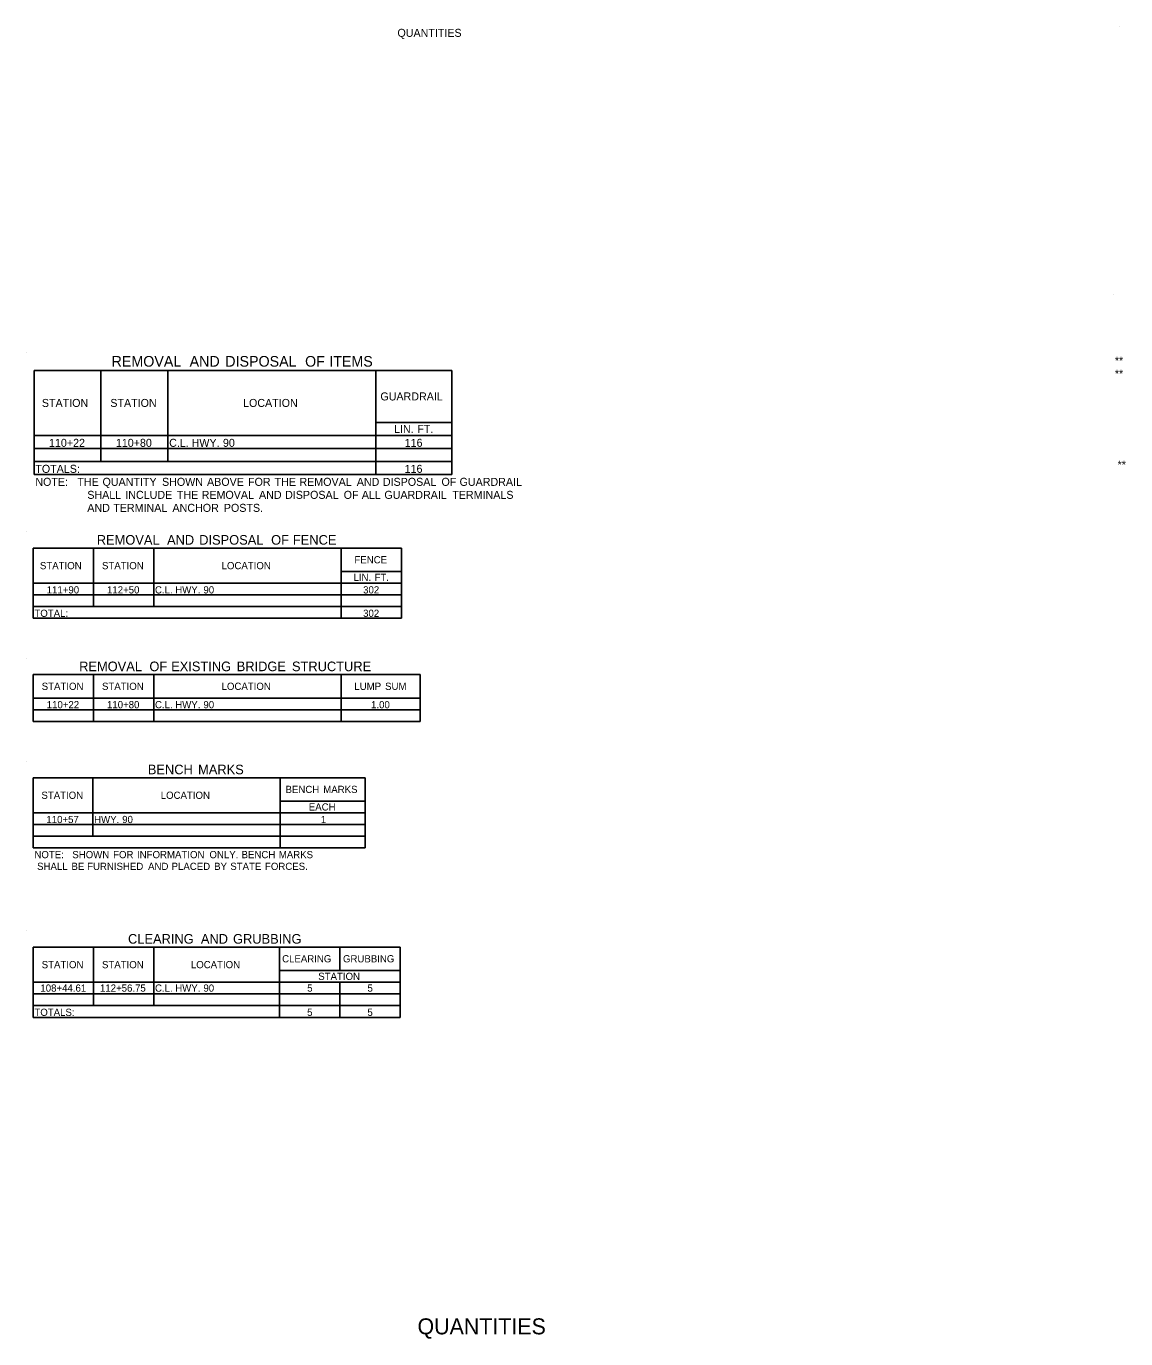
# Model space of a CAD drawing. Extents: x 120 to 5602, y 34 to 1048.
# Drawn here: x 1265 to 2090, y 34 to 1019 of the extents above; entities that cross this region are included whole.
import ezdxf

# ---------------------------------------------------------------- set-up
doc = ezdxf.new("R2010")
doc.units = 0
for name, color, linetype in [('Default', 7, 'Continuous'), ('R_Annotation', 7, 'Continuous'), ('R_Logo', 7, 'Continuous'), ('STAMP', 7, 'Continuous')]:
    doc.layers.add(name, color=color, linetype=linetype)

msp = doc.modelspace()

# ---------------------------------------------------------------- linework, layer by layer
at = {"layer": 'Default'}
for p, q in [((1270.81, 760.61), (1584.27, 760.61)), ((1270.81, 682.61), (1270.81, 760.61)), ((1270.81, 682.61), (1270.81, 760.61)), ((1321.02, 692.36), (1321.02, 760.61)), ((1371.24, 692.36), (1371.24, 760.61)), ((1527.24, 682.61), (1527.24, 760.61)), ((1584.27, 682.61), (1584.27, 760.61)), ((1584.27, 682.61), (1584.27, 760.61)), ((1527.24, 721.61), (1584.27, 721.61)), ((1270.81, 711.86), (1584.27, 711.86)), ((1321.02, 692.36), (1321.02, 711.86)), ((1371.24, 692.36), (1371.24, 711.86)), ((1527.24, 682.61), (1527.24, 711.86)), ((1270.81, 702.11), (1584.27, 702.11)), ((1270.81, 692.36), (1584.27, 692.36)), ((1527.24, 692.36), (1584.27, 692.36)), ((1270.81, 682.61), (1584.27, 682.61)), ((1270.23, 627.41), (1546.48, 627.41)), ((1270.23, 574.71), (1270.23, 627.41)), ((1270.23, 574.71), (1270.23, 627.41)), ((1315.47, 583.49), (1315.47, 627.41)), ((1360.7, 583.49), (1360.7, 627.41)), ((1501.24, 574.71), (1501.24, 627.41)), ((1546.48, 574.71), (1546.48, 627.41)), ((1546.48, 574.71), (1546.48, 627.41)), ((1270.23, 601.06), (1546.48, 601.06)), ((1315.47, 583.49), (1315.47, 601.06)), ((1360.7, 583.49), (1360.7, 601.06)), ((1501.24, 609.84), (1546.48, 609.84)), ((1501.24, 574.71), (1501.24, 601.06)), ((1270.23, 592.27), (1546.48, 592.27)), ((1270.23, 583.49), (1546.48, 583.49)), ((1270.23, 574.71), (1546.48, 574.71)), ((1270.23, 532.53), (1560.53, 532.53)), ((1270.23, 497.4), (1270.23, 532.53)), ((1270.23, 497.4), (1270.23, 532.53)), ((1315.47, 497.4), (1315.47, 532.53)), ((1360.7, 497.4), (1360.7, 532.53)), ((1501.24, 497.4), (1501.24, 532.53)), ((1560.53, 497.4), (1560.53, 532.53)), ((1560.53, 497.4), (1560.53, 532.53)), ((1270.23, 514.96), (1560.53, 514.96)), ((1315.47, 497.4), (1315.47, 514.96)), ((1360.7, 497.4), (1360.7, 514.96)), ((1501.24, 497.4), (1501.24, 514.96)), ((1270.23, 506.18), (1560.53, 506.18)), ((1270.23, 497.4), (1560.53, 497.4)), ((1270.23, 455.22), (1519.25, 455.22)), ((1270.23, 402.52), (1270.23, 455.22)), ((1270.23, 402.52), (1270.23, 455.22)), ((1315.03, 411.3), (1315.03, 455.22)), ((1455.57, 402.52), (1455.57, 455.22)), ((1519.25, 402.52), (1519.25, 455.22)), ((1455.57, 437.65), (1519.25, 437.65)), ((1519.25, 402.52), (1519.25, 437.65)), ((1270.23, 428.87), (1519.25, 428.87)), ((1455.57, 402.52), (1455.57, 428.87)), ((1270.23, 420.09), (1519.25, 420.09)), ((1270.23, 411.3), (1519.25, 411.3)), ((1270.23, 402.52), (1519.25, 402.52)), ((1270.23, 328.2), (1545.6, 328.2)), ((1270.23, 275.5), (1270.23, 328.2)), ((1270.23, 275.5), (1270.23, 328.2)), ((1315.47, 284.28), (1315.47, 328.2)), ((1360.7, 284.28), (1360.7, 328.2)), ((1455.13, 275.5), (1455.13, 328.2)), ((1500.36, 310.63), (1500.36, 328.2)), ((1545.6, 275.5), (1545.6, 328.2)), ((1545.6, 310.63), (1545.6, 328.2)), ((1455.13, 310.63), (1545.6, 310.63)), ((1455.13, 284.28), (1455.13, 310.63)), ((1270.23, 301.85), (1545.6, 301.85)), ((1315.47, 284.28), (1315.47, 301.85)), ((1360.7, 284.28), (1360.7, 301.85)), ((1500.36, 275.5), (1500.36, 301.85)), ((1500.36, 275.5), (1500.36, 301.85)), ((1545.6, 284.28), (1545.6, 301.85)), ((1270.23, 293.07), (1545.6, 293.07)), ((1270.23, 284.28), (1545.6, 284.28)), ((1360.7, 284.28), (1545.6, 284.28)), ((1270.23, 275.5), (1545.6, 275.5))]:
    msp.add_line(p, q, dxfattribs=at)
at = {"layer": 'STAMP'}
for p, q in [((2085.27, 1018.7), (2085.27, 1018.7)), ((2080.89, 817.41), (2080.89, 817.41)), ((1264.96, 774.26), (1264.96, 774.26)), ((1264.96, 639.7), (1264.96, 639.7)), ((1264.96, 544.83), (1264.96, 544.83)), ((1264.96, 467.52), (1264.96, 467.52)), ((1264.96, 340.5), (1264.96, 340.5))]:
    msp.add_line(p, q, dxfattribs=at)

# ---------------------------------------------------------------- texts
at = {"layer": 'Default'}
for s, height, p in [('REMOVAL', 8, (1329.01, 763.43)), (' AND', 8, (1384.57, 763.43)), (' DISPOSAL', 8, (1411.34, 763.43)), (' OF', 8, (1471.25, 763.43)), (' ITEMS', 8, (1489.36, 763.43)), ('**', 6, (2081.86, 764.99)), ('**', 6, (2081.86, 755.24)), ('STATION', 6, (1276.69, 733.23)), ('STATION', 6, (1328.07, 733.23)), ('LOCATION', 6, (1427.68, 733.23)), ('GUARDRAIL', 6, (1530.73, 738.11)), ('LIN.', 6, (1540.97, 713.73)), (' FT.', 6, (1556.22, 713.73)), ('110+22', 6, (1282.04, 703.31)), ('110+80', 6, (1332.23, 703.31)), ('C.L.', 6, (1372.21, 703.31)), (' HWY.', 6, (1386.85, 703.31)), (' 90', 6, (1410.33, 703.31)), ('116', 6, (1548.96, 703.31)), ('TOTALS:', 6, (1271.79, 683.81)), ('116', 6, (1548.91, 683.81)), ('**', 6, (2083.92, 686.99)), ('NOTE:', 6, (1271.79, 674.06)), ('   THE', 6, (1296.67, 674.06)), (' QUANTITY', 6, (1319.98, 674.06)), (' SHOWN', 6, (1364.63, 674.06)), (' ABOVE', 6, (1398.41, 674.06)), (' FOR', 6, (1429.18, 674.06)), (' THE', 6, (1449.09, 674.06)), (' REMOVAL', 6, (1467.74, 674.06)), (' AND', 6, (1510.77, 674.06)), (' DISPOSAL', 6, (1530.35, 674.06)), (' OF', 6, (1574.32, 674.06)), (' GUARDRAIL', 6, (1587.91, 674.06)), ('SHALL', 6, (1310.79, 664.31)), (' INCLUDE', 6, (1337.05, 664.31)), (' THE', 6, (1375.73, 664.31)), (' REMOVAL', 6, (1394.38, 664.31)), (' AND', 6, (1437.41, 664.31)), (' DISPOSAL', 6, (1456.99, 664.31)), (' OF', 6, (1500.96, 664.31)), (' ALL', 6, (1514.54, 664.31)), (' GUARDRAIL', 6, (1531.49, 664.31)), (' TERMINALS', 6, (1582.43, 664.31)), ('AND', 6, (1310.79, 654.56)), (' TERMINAL', 6, (1328.04, 654.56)), (' ANCHOR', 6, (1372.46, 654.56)), (' POSTS.', 6, (1411.01, 654.56)), ('REMOVAL', 7.207, (1317.91, 629.95)), (' AND', 7.207, (1367.96, 629.95)), (' DISPOSAL', 7.207, (1392.08, 629.95)), (' OF', 7.207, (1446.05, 629.95)), (' FENCE', 7.207, (1462.37, 629.95)), ('FENCE', 5.405, (1511.24, 615.92)), ('STATION ', 5.405, (1275.23, 611.53)), ('STATION', 5.405, (1321.81, 611.53)), ('LOCATION', 5.405, (1411.55, 611.53)), ('LIN.', 5.405, (1510.53, 602.75)), (' FT.', 5.405, (1524.28, 602.75)), ('111+90', 5.405, (1280.33, 593.35)), ('112+50', 5.405, (1325.57, 593.35)), ('C.L.', 5.405, (1361.58, 593.35)), (' HWY.', 5.405, (1374.77, 593.35)), (' 90', 5.405, (1395.92, 593.35)), ('302', 5.405, (1517.76, 593.35)), ('TOTAL:', 5.405, (1271.11, 575.79)), ('302', 5.405, (1517.75, 575.79)), ('REMOVAL', 7.207, (1304.67, 535.07)), (' OF', 7.207, (1354.72, 535.07)), (' EXISTING', 7.207, (1371.04, 535.07)), (' BRIDGE', 7.207, (1420.23, 535.07)), (' STRUCTURE', 7.207, (1461.69, 535.07)), ('STATION', 5.405, (1276.58, 521.04)), ('STATION', 5.405, (1321.81, 521.04)), ('LOCATION', 5.405, (1411.55, 521.04)), ('LUMP', 5.405, (1511.19, 521.04)), (' SUM', 5.405, (1532.24, 521.04)), ('110+22', 5.405, (1280.35, 507.26)), ('110+80', 5.405, (1325.57, 507.26)), ('C.L.', 5.405, (1361.58, 507.26)), (' HWY.', 5.405, (1374.77, 507.26)), (' 90', 5.405, (1395.92, 507.26)), ('1.00', 5.405, (1523.72, 507.26)), ('BENCH', 7.207, (1356.21, 457.76)), (' MARKS', 7.207, (1391.25, 457.76)), ('STATION', 5.405, (1276.36, 439.34)), ('LOCATION', 5.405, (1365.88, 439.34)), ('BENCH', 5.405, (1459.56, 443.73)), (' MARKS', 5.405, (1485.83, 443.73)), ('EACH', 5.405, (1477, 430.56)), ('110+57', 5.405, (1280.1, 421.17)), ('HWY.', 5.405, (1315.91, 421.17)), (' 90', 5.405, (1334.97, 421.17)), ('1', 5.41, (1486, 421.17)), ('NOTE:', 5.405, (1271.11, 394.82)), ('   SHOWN', 5.405, (1293.53, 394.82)), (' FOR', 5.405, (1328.15, 394.82)), (' INFORMATION', 5.4053, (1346.09, 394.82)), (' ONLY.', 5.405, (1400.44, 394.82)), (' BENCH', 5.405, (1424.54, 394.82)), (' MARKS', 5.405, (1452.47, 394.82)), (' SHALL', 5.405, (1271.11, 386.03)), (' BE', 5.405, (1296.87, 386.03)), (' FURNISHED', 5.405, (1308.64, 386.03)), (' AND', 5.405, (1354.39, 386.03)), (' PLACED', 5.405, (1372.03, 386.03)), (' BY', 5.405, (1403.95, 386.03)), (' STATE', 5.405, (1416.07, 386.03)), (' FORCES.', 5.405, (1442.11, 386.03)), ('CLEARING', 7.207, (1341.36, 330.75)), (' AND', 7.207, (1393.34, 330.75)), (' GRUBBING', 7.207, (1417.46, 330.75)), ('STATION', 5.405, (1276.58, 312.32)), ('STATION', 5.405, (1321.81, 312.32)), ('LOCATION', 5.405, (1388.5, 312.32)), ('CLEARING ', 5.405, (1456.97, 316.71)), ('GRUBBING', 5.405, (1502.65, 316.71)), ('STATION', 5.405, (1484.09, 303.54)), ('108+44.61', 5.405, (1275.6, 294.75)), ('112+56.75', 5.405, (1320.29, 294.75)), ('C.L.', 5.405, (1361.58, 294.75)), (' HWY.', 5.405, (1374.77, 294.75)), (' 90', 5.405, (1395.92, 294.75)), ('5', 5.41, (1475.8, 294.75)), ('5', 5.41, (1521.03, 294.75)), ('TOTALS:', 5.405, (1271.11, 276.58)), ('5', 5.41, (1475.76, 276.58)), ('5', 5.41, (1520.99, 276.58))]:
    msp.add_text(s, height=height, dxfattribs=at).set_placement(p)
at = {"layer": 'R_Annotation'}
msp.add_text('QUANTITIES', height=12, dxfattribs=at).set_placement((1558.58, 37.77))
at = {"layer": 'R_Logo'}
msp.add_text('QUANTITIES', height=6, dxfattribs=at).set_placement((1543.53, 1010.75))

doc.saveas('drawing.dxf')
